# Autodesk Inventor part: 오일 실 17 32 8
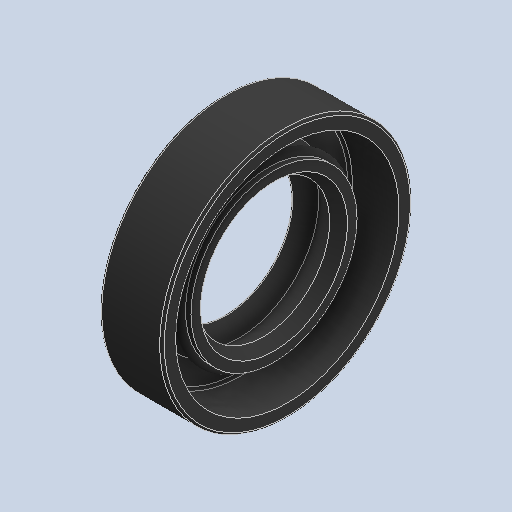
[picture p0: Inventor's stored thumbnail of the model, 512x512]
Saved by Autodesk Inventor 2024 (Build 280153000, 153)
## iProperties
Created: 2026-07
Part Number: 오일 실 17 32 8
Material: 고무
Description: 오일-실
Document SubType Name: Modeling
Designer: com
Density: 0.93 g/cm^3
Appearance: 기본값
Author: jhkim
Revision Number: 1
Sending System: Autodesk Inventor 2027
Preprocessor: ST-DEVELOPER v20.1
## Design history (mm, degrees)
node "오일 실 17 32 81"
node "솔리드1"
body "Solid1"
